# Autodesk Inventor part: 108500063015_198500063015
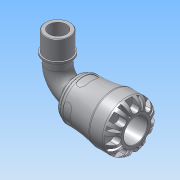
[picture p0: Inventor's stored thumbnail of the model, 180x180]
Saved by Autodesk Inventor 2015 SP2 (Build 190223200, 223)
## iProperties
Created: 2016-12
Part Number: 108500063015_198500063015
Material: PVC-Piping
Description: PLASSON 90° ELBOW WITH THREADED MALE OFFTAKE 63X1.1/2" SERIES 1
Document SubType Name: Modeling
Designer: KIM
Mass: 664.223 g
Surface Area: 733.008 cm^2
Volume: 474.445 cm^3
Density: 1.4 g/cm^3
Appearance: Smooth - White
Author: KIM
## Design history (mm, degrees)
derived "1085.ipt"
feature "Solid1::1085.ipt"
tag "TaggingFeature1"
body "Solid1"
other parameters: "d1" = 37.8, "d2" = 63, "d3" = 78.75, "d4" = 103, "d8" = 87.55, "d13" = 9.7, "d14" = 9.7, "d15" = 0, "d17" = 360 deg, "d19" = 8 deg, "d20" = 1.26, "d21" = 1.26, "d22" = 8 deg, "d24" = 0, "d26" = 360 deg, "d33" = 10.3, "d43" = 80.34, "d51" = 1.03, "d54" = 22.05, "d55" = 13.86, "d57" = 19.012, "d58" = 0, "d74" = 0, "d82" = 1.26, "d115" = 360 deg, "d207" = 90 deg, "d228" = 18.7425, "d247" = 2.06, "d248" = 5.4, "d268" = 48.1525, "d269" = 5.4, "d270" = 143, "d276" = 47.803, "d277" = 21, "d278" = 52.5833, "d279" = 78, "d280" = 23.1, "d281" = 7.17045, "d283" = 43.0227, "d286" = 0, "d287" = 0, "d288" = 33.4621, "d290" = 18.65865, "d292" = 30 deg, "d_" = 63, "E_" = 103, "A_" = 143, "A_1" = 78, "l_2" = 21, "R_" = 47.803, "d9" = 12.125, "d11" = 103, "d12" = 78.75, "d289" = 33.4621
